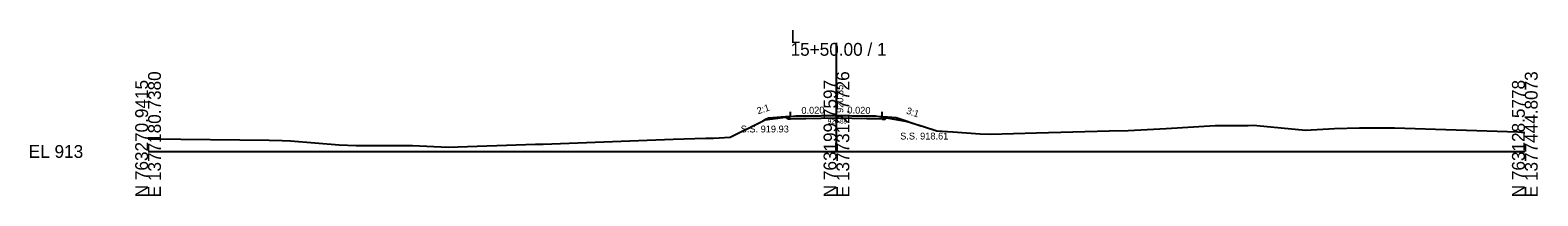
# Model space of a CAD drawing. Extents: x -26 to 303, y -10 to 6523.
# Drawn here: x -25.7 to 302.8, y 5490.3 to 5526.5 of the extents above; entities that cross this region are included whole.
import ezdxf

# ---------------------------------------------------------------- set-up
doc = ezdxf.new("R2010")
doc.units = 0
for name, color, linetype in [('Exist Cross Section Cell', 7, 'Continuous'), ('Exist XS Center Line Elevation Label', 7, 'Continuous'), ('Exist XS Ground Line', 7, 'Continuous'), ('Prop XS Dump Level', 7, 'Continuous'), ('Prop XS Elevation Labels', 7, 'Continuous'), ('Prop XS EOT Tick Mark', 7, 'Continuous'), ('Prop XS Finish Grade', 7, 'Continuous'), ('Prop XS Finish Grade Earthwork', 7, 'Continuous'), ('Prop XS Finish Grade Pavement', 7, 'Continuous'), ('Prop XS Pvmt Edge Slope', 7, 'Continuous'), ('Prop XS SE Text', 7, 'Continuous'), ('Prop XS Side Slope Text', 7, 'Continuous'), ('Prop XS SS Elevation Text', 7, 'Continuous'), ('Prop XS Subgrade Earthwork', 7, 'Continuous')]:
    doc.layers.add(name, color=color, linetype=linetype)

msp = doc.modelspace()

# ---------------------------------------------------------------- linework, layer by layer
at = {"layer": 'Exist Cross Section Cell'}
for p, q in [((150, 5500), (150, 5523.68)), ((0, 5500), (150, 5500)), ((150, 5500), (300, 5500))]:
    msp.add_line(p, q, dxfattribs=at)
at = {"layer": 'Exist XS Ground Line'}
for p, q in [((126.83, 5503.12), (134, 5506.71)), ((134, 5506.71), (134.4, 5506.93)), ((134.4, 5506.93), (141.15, 5507.76)), ((141.15, 5507.76), (146.73, 5507.85)), ((146.73, 5507.85), (149.85, 5507.89)), ((149.85, 5507.89), (152.9, 5507.84)), ((152.9, 5507.84), (158.41, 5507.76)), ((158.41, 5507.76), (163.82, 5506.86)), ((163.82, 5506.86), (165.39, 5506.56)), ((165.39, 5506.56), (169, 5505.42)), ((123.22, 5502.91), (126.83, 5503.12)), ((169, 5505.42), (171.86, 5504.5)), ((171.86, 5504.5), (175.34, 5504.28)), ((175.34, 5504.28), (181.33, 5503.86)), ((181.33, 5503.86), (183.57, 5503.74)), ((183.57, 5503.74), (193.58, 5504.07)), ((193.58, 5504.07), (209.4, 5504.47)), ((209.4, 5504.47), (213.59, 5504.59)), ((213.59, 5504.59), (221.88, 5505.02)), ((221.88, 5505.02), (232.54, 5505.63)), ((232.54, 5505.63), (239.72, 5505.7)), ((239.72, 5505.7), (240.87, 5505.72)), ((240.87, 5505.72), (241.64, 5505.66)), ((241.64, 5505.66), (252.21, 5504.62)), ((252.21, 5504.62), (258.5, 5505.03)), ((258.5, 5505.03), (263.96, 5505.13)), ((263.96, 5505.13), (271.61, 5505.19)), ((271.61, 5505.19), (298.46, 5504.25)), ((298.46, 5504.25), (300, 5504.17)), ((0, 5502.75), (0.78, 5502.75)), ((0.78, 5502.75), (26.37, 5502.44)), ((26.37, 5502.44), (29.19, 5502.42)), ((29.19, 5502.42), (31.01, 5502.33)), ((31.01, 5502.33), (41.67, 5501.46)), ((41.67, 5501.46), (45.37, 5501.32)), ((45.37, 5501.32), (57.59, 5501.29)), ((57.59, 5501.29), (65.36, 5500.96)), ((65.36, 5500.96), (84.46, 5501.56)), ((84.46, 5501.56), (85.53, 5501.57)), ((85.53, 5501.57), (86.1, 5501.59)), ((86.1, 5501.59), (88, 5501.66)), ((88, 5501.66), (114.39, 5502.67)), ((114.39, 5502.67), (121.54, 5502.9)), ((121.54, 5502.9), (123.22, 5502.91))]:
    msp.add_line(p, q, dxfattribs=at)
at = {"layer": 'Prop XS Dump Level'}
for p, q in [((140, 5507.65), (150, 5507.85)), ((150, 5507.85), (160, 5507.65))]:
    msp.add_line(p, q, dxfattribs=at)
at = {"layer": 'Prop XS EOT Tick Mark'}
for p, q in [((140, 5507.65), (140, 5508.65)), ((160, 5507.65), (160, 5508.65))]:
    msp.add_line(p, q, dxfattribs=at)
at = {"layer": 'Prop XS Finish Grade'}
for p, q in [((140, 5507.65), (138.9, 5507.56)), ((160, 5507.65), (161.1, 5507.56))]:
    msp.add_line(p, q, dxfattribs=at)
at = {"layer": 'Prop XS Finish Grade Earthwork'}
for p, q in [((135.22, 5507.26), (134.4, 5506.93)), ((138.9, 5507.56), (135.22, 5507.26)), ((161.1, 5507.56), (163, 5507.41)), ((163, 5507.41), (168.39, 5505.61))]:
    msp.add_line(p, q, dxfattribs=at)
at = {"layer": 'Prop XS Finish Grade Pavement'}
for p, q in [((140, 5507.65), (150, 5507.85)), ((150, 5507.85), (160, 5507.65))]:
    msp.add_line(p, q, dxfattribs=at)
at = {"layer": 'Prop XS Pvmt Edge Slope'}
for p, q in [((140, 5507.65), (139.4, 5507.05)), ((160, 5507.65), (160.6, 5507.05))]:
    msp.add_line(p, q, dxfattribs=at)
at = {"layer": 'Prop XS Subgrade Earthwork'}
for p, q in [((139.4, 5507.05), (138.9, 5507.56)), ((140, 5507.06), (139.4, 5507.05)), ((150, 5507.26), (140, 5507.06)), ((160, 5507.06), (150, 5507.26)), ((160, 5507.06), (160.6, 5507.05)), ((160.6, 5507.05), (161.1, 5507.56))]:
    msp.add_line(p, q, dxfattribs=at)

# ---------------------------------------------------------------- texts
at = {"layer": 'Exist Cross Section Cell'}
for s, p in [('L', (140, 5523.68)), ('15+50.00 / 1', (140, 5520.88)), ('EL 913', (-26, 5498.6))]:
    msp.add_text(s, height=2.8, dxfattribs=at).set_placement(p)
for s, p in [('E 1377180.7380', (2.8, 5490)), ('E 1377312.7726', (152.8, 5490)), ('E 1377444.8073', (302.8, 5490)), ('N 763270.9415', (0, 5490)), ('N 763199.7597', (150, 5490)), ('N 763128.5778', (300, 5490))]:
    msp.add_text(s, height=2.8, rotation=90, dxfattribs=at).set_placement(p)
at = {"layer": 'Exist XS Center Line Elevation Label'}
msp.add_text('920.89', height=0.998, dxfattribs=at).set_placement((148.1, 5506.09))
at = {"layer": 'Prop XS Dump Level'}
for p in [(137, 5507.37), (163, 5507.37)]:
    msp.add_text('Case1', height=0.04, dxfattribs=at).set_placement(p)
at = {"layer": 'Prop XS Elevation Labels'}
msp.add_text(' 920.85', height=1.5, rotation=90, dxfattribs=at).set_placement((151.5, 5507.85))
at = {"layer": 'Prop XS SE Text'}
for rotation, p in [(1.1458, (142.38, 5508.19)), (358.8542, (152.38, 5508.3))]:
    msp.add_text('0.020', height=1.5, rotation=rotation, dxfattribs=at).set_placement(p)
at = {"layer": 'Prop XS Side Slope Text'}
for s, rotation, p in [('2:1', 18.4349, (132.94, 5508.09)), ('3:1', 341.5651, (165.08, 5508.29))]:
    msp.add_text(s, height=1.5, rotation=rotation, dxfattribs=at).set_placement(p)
at = {"layer": 'Prop XS SS Elevation Text'}
for s, p in [('S.S. 919.93', (129.14, 5504.15)), ('S.S. 918.61', (163.89, 5502.61))]:
    msp.add_text(s, height=1.5, dxfattribs=at).set_placement(p)

doc.saveas('drawing.dxf')
